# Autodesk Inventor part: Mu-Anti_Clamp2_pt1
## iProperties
Shininess: 64.0
Length Units: 11272
Angle Units: 11279
Time Units: 11290
Mass Units: 11286
Length Display Precision: 3
Angle Display Precision: 2
Compacted: True
Part Number: Mu-Anti_Clamp2_pt1
Document SubType Name: Modeling
Created: 2004-08
Designer: John Blackburn
Material: Aluminum-6061
Manufacturer: Standard
Standards Organization: Custom
Density: 0.0
Volumn: 0.0
Area: 0.0
PropertySet Name: Model Information
Control State: 0
Master: False
Checked Out: False
Author: John Blackburn
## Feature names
1. Extrusion1
2. Split1
